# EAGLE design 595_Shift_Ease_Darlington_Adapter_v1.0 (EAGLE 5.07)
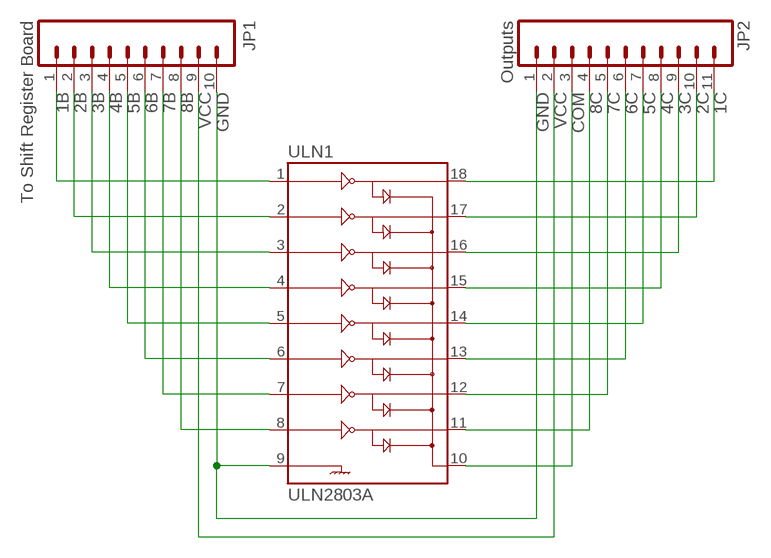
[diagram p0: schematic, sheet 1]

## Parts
JP1  To Shift Register Board  M101X10_M_H  [1X10_M_H]
JP2  Outputs  M11PTH  [1X11]
ULN1  ULN2803A  ULN2803DIP  [DIL18]

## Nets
1B: JP1.1 ULN1.1
1C: JP2.11 ULN1.18
2B: JP1.2 ULN1.2
2C: JP2.10 ULN1.17
3B: JP1.3 ULN1.3
3C: JP2.9 ULN1.16
4B: JP1.4 ULN1.4
4C: JP2.8 ULN1.15
5B: JP1.5 ULN1.5
5C: JP2.7 ULN1.14
6B: JP1.6 ULN1.6
6C: JP2.6 ULN1.13
7B: JP1.7 ULN1.7
7C: JP2.5 ULN1.12
8B: JP1.8 ULN1.8
8C: JP2.4 ULN1.11
COM: JP2.3 ULN1.10
GND: JP1.10 JP2.1 ULN1.9
VCC: JP1.9 JP2.2

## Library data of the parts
JP1 = SparkFun:M10: Header 10 Standard 10-pin 0.1" header. Use with straight break away headers (SKU : PRT-00116), right angle break away headers (PRT-00553), swiss pins (PRT-00743), machine pins (PRT-00117), and female headers (PRT-00115).
JP2 = SparkFun:M11: Header 11 Standard 11-pin 0.1" header. Use with straight break away headers (SKU : PRT-00116), right angle break away headers (PRT-00553), swiss pins (PRT-00743), machine pins (PRT-00117), and female headers (PRT-00115).
ULN1 = SparkFun:ULN2803: Darlington Driver ULN2803 Darlington array. 500mA max per channel, 8-channel package. Spark Fun Electronics SKU : COM-00312

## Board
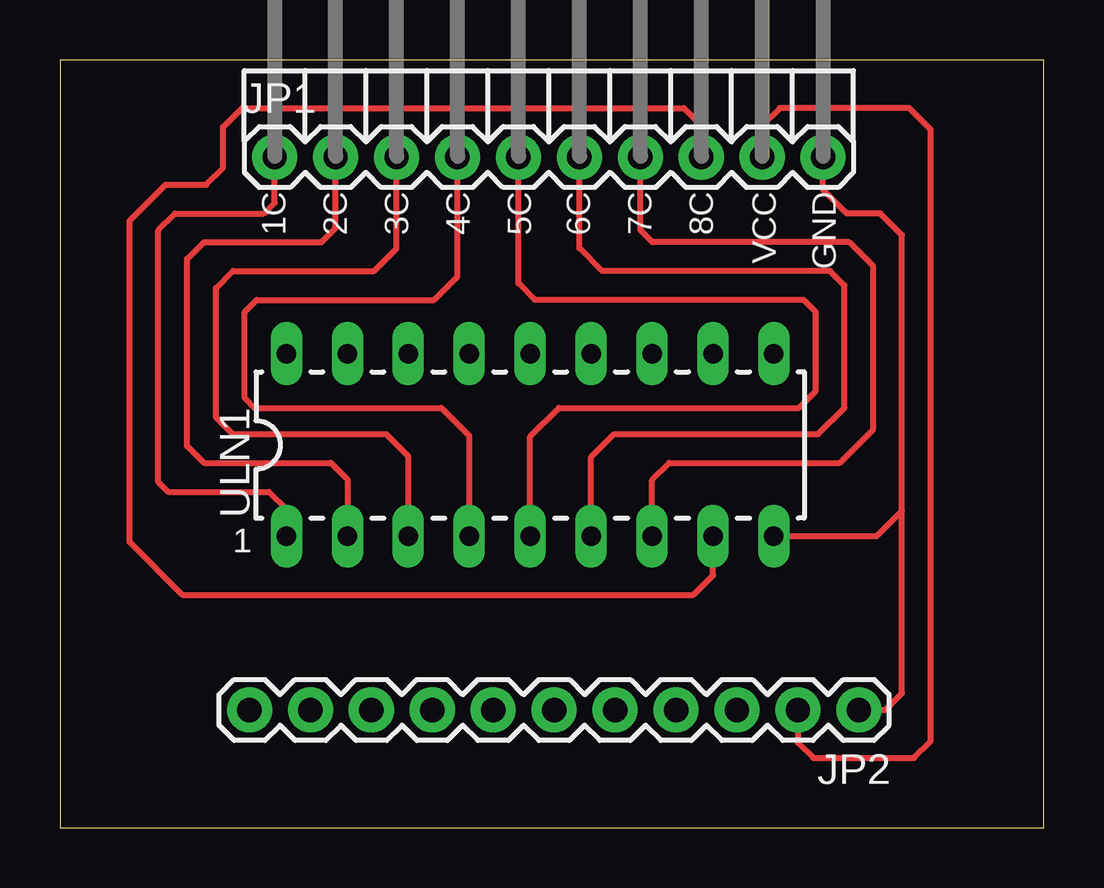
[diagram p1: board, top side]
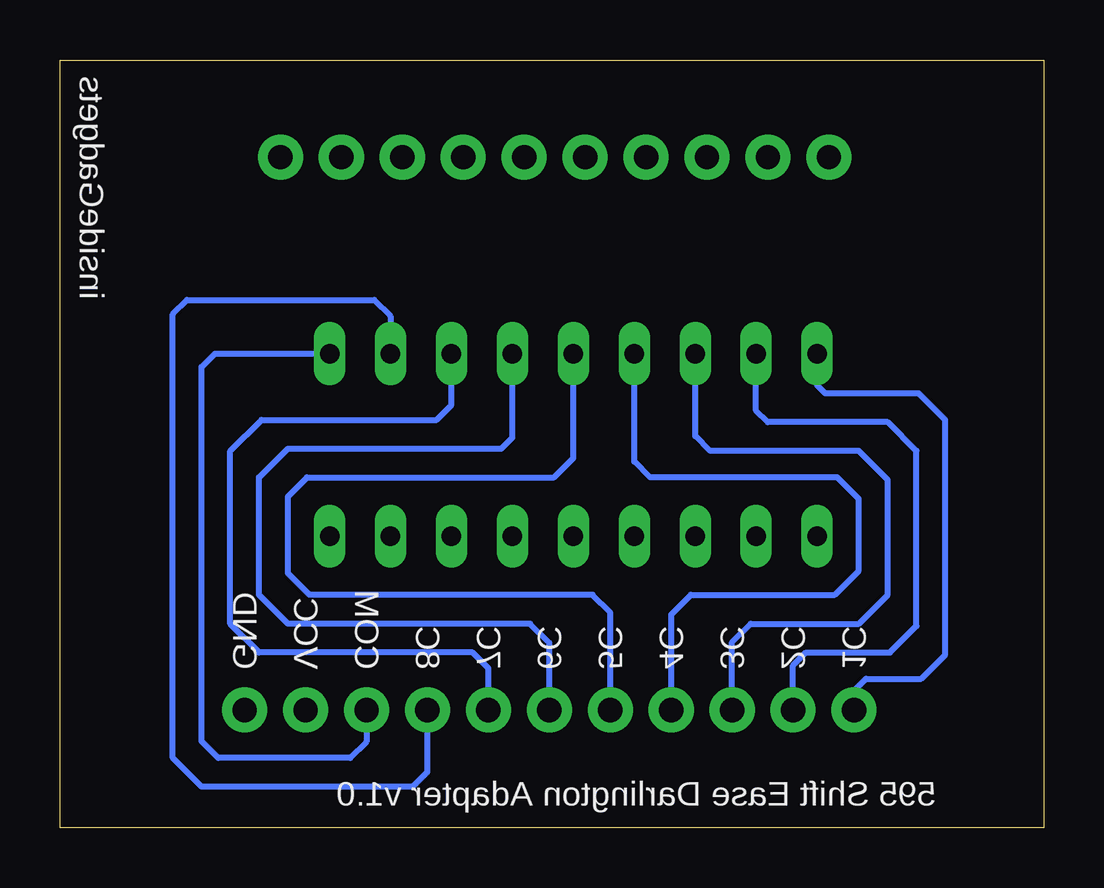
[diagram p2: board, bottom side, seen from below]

Size 41 x 32 mm. Coordinates in mm from the lower left corner, seen from the top.
Outline: 0,0 41,0 41,32 0,32 0,0
Copper layers (1*16): Top 0.035mm / dielectric 1.5mm / Bottom 0.035mm
Design rules "default": minimum track width 10mil, minimum drill 24mil, track to track 8mil, track to pad 8mil, pad to pad 8mil, via to via 8mil, smd to smd 8mil, copper to edge 40mil, drill to drill 8mil, minimum pad ring 10mil, minimum via ring 8mil, stop-mask expansion 4mil, vias tented up to drill 0mil, thermal gap 10mil

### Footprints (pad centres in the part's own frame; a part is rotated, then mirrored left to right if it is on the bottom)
1X10_M_H = drill 1.016 pad 1.88 round: 1 0,0; 2 2.54,0; 3 5.08,0; 4 7.62,0; 5 10.16,0; 6 12.7,0; 7 15.24,0; 8 17.78,0; 9 20.32,0; 10 22.86,0
1X11 = drill 1.016 pad 1.88 round: 1 0,0; 2 2.54,0; 3 5.08,0; 4 7.62,0; 5 10.16,0; 6 12.7,0; 7 15.24,0; 8 17.78,0; 9 20.32,0; 10 22.86,0; 11 25.4,0
DIL18 = drill 0.813 long: 1 -10.16,-3.81; 2 -7.62,-3.81; 3 -5.08,-3.81; 4 -2.54,-3.81; 5 0,-3.81; 6 2.54,-3.81; 7 5.08,-3.81; 8 7.62,-3.81; 9 10.16,-3.81; 10 10.16,3.81; 11 7.62,3.81; 12 5.08,3.81; 13 2.54,3.81; 14 0,3.81; 15 -2.54,3.81; 16 -5.08,3.81; 17 -7.62,3.81; 18 -10.16,3.81

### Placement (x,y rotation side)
JP1  8.95,27.95 0 top
JP2  33.3,4.9 180 top
ULN1  19.6,15.95 0 top

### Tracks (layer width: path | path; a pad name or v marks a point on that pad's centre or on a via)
1B
  Top 0.254: ULN1.1 9.44,13.26 8.7,14 4.5,14 4.1,14.4 4.1,24.9 4.8,25.6 8.5,25.6 8.95,26.05 JP1.1
1C
  Bottom 0.254: ULN1.18 9.44,18.44 9.1,18.1 5.2,18.1 4.1,17 4.1,7.2 5.1,6.2 7.4,6.2 7.9,5.7 JP2.11
2B
  Top 0.254: ULN1.2 11.98,14.52 11.3,15.2 6,15.2 5.3,15.9 5.3,23.7 6,24.4 10.9,24.4 11.49,24.99 JP1.2
2C
  Bottom 0.254: ULN1.17 11.98,17.38 11.5,16.9 6.5,16.9 5.3,15.7 5.3,8.4 6.4,7.3 9.9,7.3 10.44,6.76 JP2.10
3B
  Top 0.254: ULN1.3 14.52,15.48 13.6,16.4 7.2,16.4 6.5,17.1 6.5,22.5 7.2,23.2 13.1,23.2 14.03,24.13 JP1.3
3C
  Bottom 0.254: ULN1.16 14.52,16.32 13.9,15.7 7.7,15.7 6.5,14.5 6.5,9.7 7.7,8.5 12.2,8.5 12.98,7.72 JP2.9
4B
  Top 0.254: ULN1.4 17.06,16.34 15.9,17.5 8.1,17.5 7.7,17.9 7.7,21.5 8.2,22 15.6,22 16.57,22.97 JP1.4
4C
  Bottom 0.254: JP2.8 15.52,8.88 14.7,9.7 8.7,9.7 7.7,10.7 7.7,13.7 8.6,14.6 16.4,14.6 17.06,15.26 ULN1.15
5B
  Top 0.254: JP1.5 19.11,22.69 19.8,22 31,22 31.5,21.5 31.5,18.2 30.8,17.5 20.8,17.5 19.6,16.3 ULN1.5
5C
  Bottom 0.254: ULN1.14 19.6,15.4 20.4,14.6 30.7,14.6 31.5,13.8 31.5,10.6 30.6,9.7 18.8,9.7 18.06,8.96 JP2.7
6B
  Top 0.254: ULN1.6 22.14,15.44 23.1,16.4 31.6,16.4 32.7,17.5 32.7,22.6 32.1,23.2 22.6,23.2 21.65,24.15 JP1.6
6C
  Bottom 0.254: ULN1.13 22.14,16.26 22.6,15.8 31.5,15.8 32.7,14.6 32.7,9.7 31.5,8.5 21.4,8.5 20.6,7.7 JP2.6
7B
  Top 0.254: JP1.7 24.19,24.91 24.7,24.4 32.9,24.4 33.9,23.4 33.9,16.6 32.5,15.2 25.4,15.2 24.68,14.48 ULN1.7
7C
  Bottom 0.254: ULN1.12 24.68,17.62 25.3,17 32.6,17 33.9,15.7 33.9,8.5 32.7,7.3 23.8,7.3 23.14,6.64 JP2.5
8B
  Top 0.254: JP1.8 26.73,29.27 26,30 7.6,30 6.8,29.2 6.8,27.5 6.1,26.8 4.4,26.8 2.9,25.3 2.9,11.9 5.1,9.7 26.4,9.7 27.22,10.52 ULN1.8
8C
  Bottom 0.254: ULN1.11 27.22,21.32 27.9,22 35.7,22 36.3,21.4 36.3,2.9 35.1,1.7 26.3,1.7 25.68,2.32 JP2.4
COM
  Bottom 0.254: ULN1.10 34.54,19.76 35.1,19.2 35.1,3.6 34.4,2.9 28.9,2.9 28.22,3.58 JP2.3
GND
  Top 0.254: JP1.10 31.81,26.59 32.8,25.6 34.2,25.6 35.1,24.7 35.1,13.2 | 35.1,13.2 35.1,5.6 34.4,4.9 JP2.1 | ULN1.9 34.04,12.14 35.1,13.2
VCC
  Top 0.254: JP1.9 29.27,29.27 30,30 35.4,30 36.3,29.1 36.3,3.6 35.6,2.9 31.4,2.9 30.76,3.54 JP2.2

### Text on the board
tPlace: 1C | 2C | 3C | 4C | 5C | 6C | 7C | 8C | VCC | GND | 1
bPlace: insideGadgets | 1C | 2C | 3C | 4C | 5C | 6C | 7C | 8C | COM | VCC | GND | 595 Shift Ease Darlington Adapter v1.0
